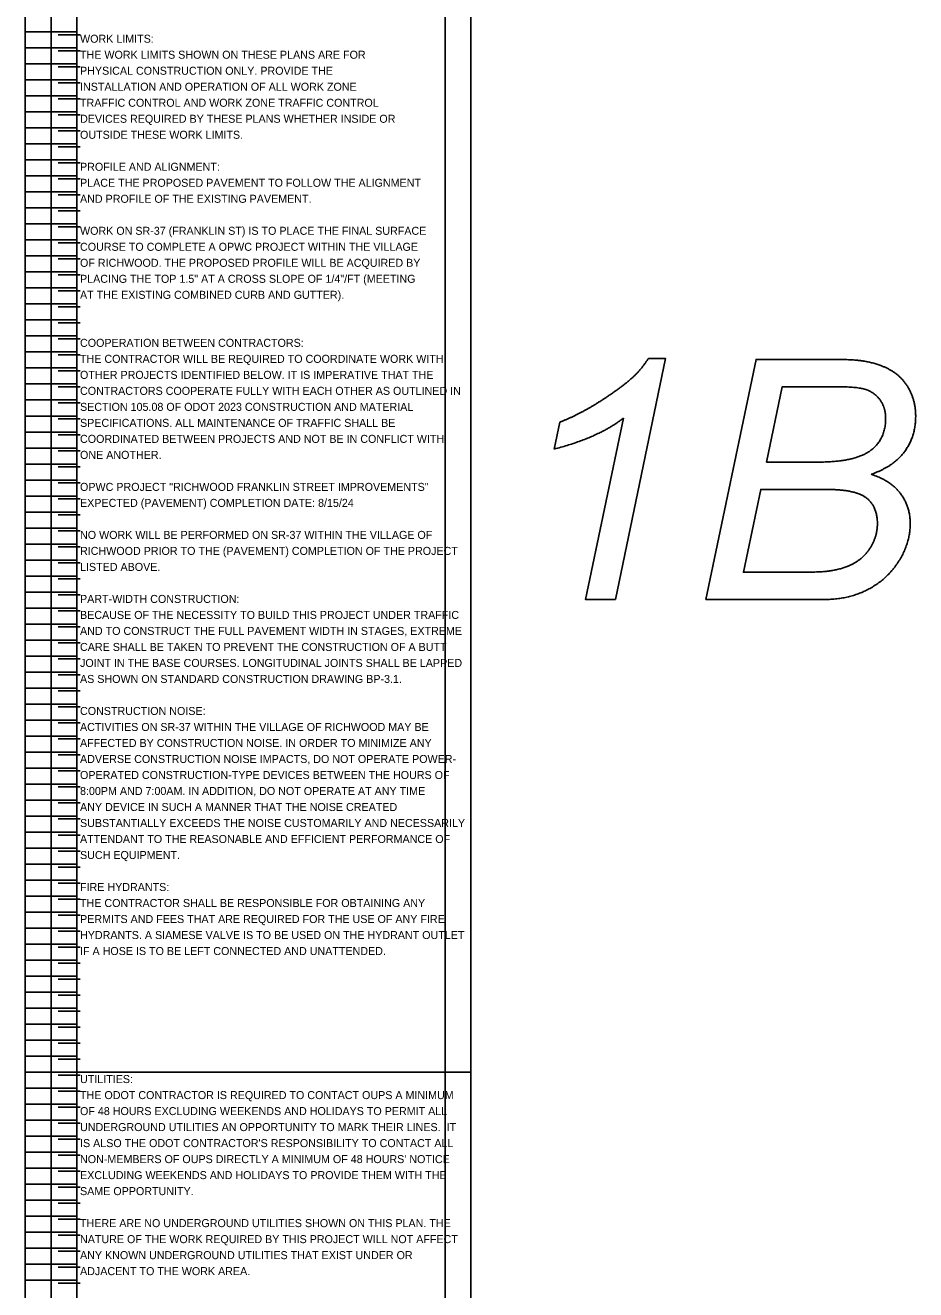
# Model space of a CAD drawing. Extents: x 12316 to 12541, y 1124 to 1850.
# Drawn here: x 12521.92 to 12537.48, y 1805.67 to 1827.79 of the extents above; entities that cross this region are included whole.
import ezdxf

# ---------------------------------------------------------------- set-up
doc = ezdxf.new("R2010")
doc.units = 0
for name, color, linetype in [('SC_Scratch1', 7, 'Continuous'), ('SH_Data', 7, 'Continuous'), ('SH_Text', 7, 'Continuous')]:
    doc.layers.add(name, color=color, linetype=linetype)

msp = doc.modelspace()

# ---------------------------------------------------------------- linework, layer by layer
at = {"layer": 'SC_Scratch1'}
for p, q in [((12521.919, 1809.471), (12521.919, 1829.631)), ((12522.819, 1809.471), (12522.819, 1829.631)), ((12522.819, 1809.471), (12522.819, 1829.631)), ((12522.819, 1829.631), (12522.819, 1809.471)), ((12529.259, 1829.631), (12529.259, 1809.471)), ((12521.919, 1827.671), (12522.819, 1827.671)), ((12522.876, 1827.621), (12522.492, 1827.621)), ((12521.919, 1827.391), (12522.819, 1827.391)), ((12522.876, 1827.341), (12522.492, 1827.341)), ((12521.919, 1827.111), (12522.819, 1827.111)), ((12522.876, 1827.061), (12522.492, 1827.061)), ((12521.919, 1826.831), (12522.819, 1826.831)), ((12522.876, 1826.781), (12522.492, 1826.781)), ((12521.919, 1826.551), (12522.819, 1826.551)), ((12522.876, 1826.501), (12522.492, 1826.501)), ((12521.919, 1826.271), (12522.819, 1826.271)), ((12522.876, 1826.221), (12522.492, 1826.221)), ((12521.919, 1825.991), (12522.819, 1825.991)), ((12522.876, 1825.941), (12522.492, 1825.941)), ((12521.919, 1825.711), (12522.819, 1825.711)), ((12522.876, 1825.661), (12522.492, 1825.661)), ((12521.919, 1825.431), (12522.819, 1825.431)), ((12522.876, 1825.381), (12522.492, 1825.381)), ((12521.919, 1825.151), (12522.819, 1825.151)), ((12522.876, 1825.101), (12522.492, 1825.101)), ((12521.919, 1824.871), (12522.819, 1824.871)), ((12522.876, 1824.821), (12522.492, 1824.821)), ((12521.919, 1824.591), (12522.819, 1824.591)), ((12522.876, 1824.541), (12522.492, 1824.541)), ((12521.919, 1824.311), (12522.819, 1824.311)), ((12522.876, 1824.261), (12522.492, 1824.261)), ((12521.919, 1824.031), (12522.819, 1824.031)), ((12522.876, 1823.981), (12522.492, 1823.981)), ((12521.919, 1823.751), (12522.819, 1823.751)), ((12522.876, 1823.701), (12522.492, 1823.701)), ((12521.919, 1823.471), (12522.819, 1823.471)), ((12522.876, 1823.421), (12522.492, 1823.421)), ((12521.919, 1823.191), (12522.819, 1823.191)), ((12522.876, 1823.141), (12522.492, 1823.141)), ((12521.919, 1822.911), (12522.819, 1822.911)), ((12522.876, 1822.861), (12522.492, 1822.861)), ((12521.919, 1822.631), (12522.819, 1822.631)), ((12522.876, 1822.581), (12522.492, 1822.581)), ((12521.919, 1822.351), (12522.819, 1822.351)), ((12522.876, 1822.301), (12522.492, 1822.301)), ((12521.919, 1822.071), (12522.819, 1822.071)), ((12522.876, 1822.021), (12522.492, 1822.021)), ((12521.919, 1821.791), (12522.819, 1821.791)), ((12522.876, 1821.741), (12522.492, 1821.741)), ((12521.919, 1821.511), (12522.819, 1821.511)), ((12522.876, 1821.461), (12522.492, 1821.461)), ((12521.919, 1821.231), (12522.819, 1821.231)), ((12522.876, 1821.181), (12522.492, 1821.181)), ((12521.919, 1820.951), (12522.819, 1820.951)), ((12522.876, 1820.901), (12522.492, 1820.901)), ((12531.166, 1820.372), (12531.263, 1820.843)), ((12521.919, 1820.671), (12522.819, 1820.671)), ((12522.876, 1820.621), (12522.492, 1820.621)), ((12521.919, 1820.391), (12522.819, 1820.391)), ((12522.876, 1820.341), (12522.492, 1820.341)), ((12521.919, 1820.111), (12522.819, 1820.111)), ((12522.876, 1820.061), (12522.492, 1820.061)), ((12521.919, 1819.831), (12522.819, 1819.831)), ((12522.876, 1819.781), (12522.492, 1819.781)), ((12521.919, 1819.551), (12522.819, 1819.551)), ((12522.876, 1819.501), (12522.492, 1819.501)), ((12521.919, 1819.271), (12522.819, 1819.271)), ((12522.876, 1819.221), (12522.492, 1819.221)), ((12521.919, 1818.991), (12522.819, 1818.991)), ((12522.876, 1818.941), (12522.492, 1818.941)), ((12521.919, 1818.711), (12522.819, 1818.711)), ((12522.876, 1818.661), (12522.492, 1818.661)), ((12521.919, 1818.431), (12522.819, 1818.431)), ((12522.876, 1818.381), (12522.492, 1818.381)), ((12521.919, 1818.151), (12522.819, 1818.151)), ((12522.876, 1818.101), (12522.492, 1818.101)), ((12521.919, 1817.871), (12522.819, 1817.871)), ((12522.876, 1817.821), (12522.492, 1817.821)), ((12521.919, 1817.591), (12522.819, 1817.591)), ((12522.876, 1817.541), (12522.492, 1817.541)), ((12521.919, 1817.311), (12522.819, 1817.311)), ((12522.876, 1817.261), (12522.492, 1817.261)), ((12521.919, 1817.031), (12522.819, 1817.031)), ((12522.876, 1816.981), (12522.492, 1816.981)), ((12521.919, 1816.751), (12522.819, 1816.751)), ((12522.876, 1816.701), (12522.492, 1816.701)), ((12521.919, 1816.471), (12522.819, 1816.471)), ((12522.876, 1816.421), (12522.492, 1816.421)), ((12521.919, 1816.191), (12522.819, 1816.191)), ((12522.876, 1816.141), (12522.492, 1816.141)), ((12521.919, 1815.911), (12522.819, 1815.911)), ((12522.876, 1815.861), (12522.492, 1815.861)), ((12521.919, 1815.631), (12522.819, 1815.631)), ((12522.876, 1815.581), (12522.492, 1815.581)), ((12521.919, 1815.351), (12522.819, 1815.351)), ((12522.876, 1815.301), (12522.492, 1815.301)), ((12521.919, 1815.071), (12522.819, 1815.071)), ((12522.876, 1815.021), (12522.492, 1815.021)), ((12521.919, 1814.791), (12522.819, 1814.791)), ((12522.876, 1814.741), (12522.492, 1814.741)), ((12521.919, 1814.511), (12522.819, 1814.511)), ((12522.876, 1814.461), (12522.492, 1814.461)), ((12521.919, 1814.231), (12522.819, 1814.231)), ((12522.876, 1814.181), (12522.492, 1814.181)), ((12521.919, 1813.951), (12522.819, 1813.951)), ((12522.876, 1813.901), (12522.492, 1813.901)), ((12521.919, 1813.671), (12522.819, 1813.671)), ((12522.876, 1813.621), (12522.492, 1813.621)), ((12521.919, 1813.391), (12522.819, 1813.391)), ((12522.876, 1813.341), (12522.492, 1813.341)), ((12521.919, 1813.111), (12522.819, 1813.111)), ((12522.876, 1813.061), (12522.492, 1813.061)), ((12521.919, 1812.831), (12522.819, 1812.831)), ((12522.876, 1812.781), (12522.492, 1812.781)), ((12521.919, 1812.551), (12522.819, 1812.551)), ((12522.876, 1812.501), (12522.492, 1812.501)), ((12521.919, 1812.271), (12522.819, 1812.271)), ((12522.876, 1812.221), (12522.492, 1812.221)), ((12521.919, 1811.991), (12522.819, 1811.991)), ((12522.876, 1811.941), (12522.492, 1811.941)), ((12521.919, 1811.711), (12522.819, 1811.711)), ((12522.876, 1811.661), (12522.492, 1811.661)), ((12521.919, 1811.431), (12522.819, 1811.431)), ((12522.876, 1811.381), (12522.492, 1811.381)), ((12521.919, 1811.151), (12522.819, 1811.151)), ((12522.876, 1811.101), (12522.492, 1811.101)), ((12521.919, 1810.871), (12522.819, 1810.871)), ((12522.876, 1810.821), (12522.492, 1810.821)), ((12521.919, 1810.591), (12522.819, 1810.591)), ((12522.876, 1810.541), (12522.492, 1810.541)), ((12521.919, 1810.311), (12522.819, 1810.311)), ((12522.876, 1810.261), (12522.492, 1810.261)), ((12521.919, 1810.031), (12522.819, 1810.031)), ((12522.876, 1809.981), (12522.492, 1809.981)), ((12521.919, 1809.751), (12522.819, 1809.751)), ((12522.876, 1809.701), (12522.492, 1809.701)), ((12521.919, 1809.471), (12522.819, 1809.471)), ((12521.919, 1789.311), (12521.919, 1809.471)), ((12521.919, 1809.471), (12522.819, 1809.471)), ((12522.876, 1809.421), (12522.492, 1809.421)), ((12529.259, 1809.471), (12522.819, 1809.471)), ((12522.819, 1789.311), (12522.819, 1809.471)), ((12522.819, 1809.471), (12529.259, 1809.471)), ((12522.819, 1789.311), (12522.819, 1809.471)), ((12522.819, 1809.471), (12522.819, 1789.311)), ((12529.259, 1809.471), (12529.259, 1789.311)), ((12521.919, 1809.191), (12522.819, 1809.191)), ((12522.876, 1809.141), (12522.492, 1809.141)), ((12521.919, 1808.911), (12522.819, 1808.911)), ((12522.876, 1808.861), (12522.492, 1808.861)), ((12521.919, 1808.631), (12522.819, 1808.631)), ((12522.876, 1808.581), (12522.492, 1808.581)), ((12521.919, 1808.351), (12522.819, 1808.351)), ((12522.876, 1808.301), (12522.492, 1808.301)), ((12521.919, 1808.071), (12522.819, 1808.071)), ((12522.876, 1808.021), (12522.492, 1808.021)), ((12521.919, 1807.791), (12522.819, 1807.791)), ((12522.876, 1807.741), (12522.492, 1807.741)), ((12521.919, 1807.511), (12522.819, 1807.511)), ((12522.876, 1807.461), (12522.492, 1807.461)), ((12521.919, 1807.231), (12522.819, 1807.231)), ((12522.876, 1807.181), (12522.492, 1807.181)), ((12521.919, 1806.951), (12522.819, 1806.951)), ((12522.876, 1806.901), (12522.492, 1806.901)), ((12521.919, 1806.671), (12522.819, 1806.671)), ((12522.876, 1806.621), (12522.492, 1806.621)), ((12521.919, 1806.391), (12522.819, 1806.391)), ((12522.876, 1806.341), (12522.492, 1806.341)), ((12521.919, 1806.111), (12522.819, 1806.111)), ((12522.876, 1806.061), (12522.492, 1806.061)), ((12521.919, 1805.831), (12522.819, 1805.831)), ((12522.876, 1805.781), (12522.492, 1805.781))]:
    msp.add_line(p, q, dxfattribs=at)
for points in [[(12522.369, 1829.631), (12529.709, 1829.631), (12529.709, 1809.471), (12522.369, 1809.471)], [(12522.369, 1809.471), (12529.709, 1809.471), (12529.709, 1789.311), (12522.369, 1789.311)]]:
    msp.add_lwpolyline(points, close=True, dxfattribs=at)
for points in [[(12532.811, 1821.957), (12533.111, 1821.957), (12532.234, 1817.741), (12531.712, 1817.741), (12532.375, 1820.914)], [(12536.034, 1821.941), (12534.693, 1821.941), (12533.816, 1817.741), (12535.897, 1817.741)], [(12535.771, 1820.145), (12534.877, 1820.145), (12535.152, 1821.464), (12536.09, 1821.464)], [(12535.467, 1818.218), (12534.474, 1818.218), (12534.777, 1819.668), (12535.893, 1819.668)]]:
    msp.add_lwpolyline(points, dxfattribs=at)
for points in [[(12532.593, 1821.68), (12532.707, 1821.794), (12532.811, 1821.957)], [(12536.577, 1821.912), (12536.4, 1821.941), (12536.034, 1821.941)], [(12537.066, 1821.741), (12536.867, 1821.863), (12536.577, 1821.912)], [(12532.027, 1821.246), (12532.404, 1821.494), (12532.593, 1821.68)], [(12537.375, 1821.409), (12537.266, 1821.62), (12537.066, 1821.741)], [(12536.09, 1821.464), (12536.493, 1821.464), (12536.639, 1821.405)], [(12536.639, 1821.405), (12536.785, 1821.346), (12536.872, 1821.217)], [(12537.484, 1820.943), (12537.484, 1821.198), (12537.375, 1821.409)], [(12531.263, 1820.843), (12531.65, 1820.997), (12532.027, 1821.246)], [(12536.872, 1821.217), (12536.959, 1821.087), (12536.959, 1820.909)], [(12537.293, 1820.332), (12537.484, 1820.596), (12537.484, 1820.943)], [(12532.375, 1820.914), (12531.945, 1820.576), (12531.166, 1820.372)], [(12536.959, 1820.909), (12536.959, 1820.536), (12536.686, 1820.34)], [(12536.686, 1820.34), (12536.413, 1820.145), (12535.771, 1820.145)], [(12536.707, 1819.931), (12537.101, 1820.068), (12537.293, 1820.332)], [(12537.219, 1819.594), (12537.049, 1819.819), (12536.707, 1819.931)], [(12535.893, 1819.668), (12536.437, 1819.668), (12536.626, 1819.515)], [(12537.388, 1819.069), (12537.388, 1819.37), (12537.219, 1819.594)], [(12536.626, 1819.515), (12536.815, 1819.362), (12536.815, 1819.067)], [(12536.815, 1819.067), (12536.815, 1818.87), (12536.717, 1818.69)], [(12537.185, 1818.405), (12537.388, 1818.723), (12537.388, 1819.069)], [(12536.717, 1818.69), (12536.619, 1818.51), (12536.447, 1818.399)], [(12536.447, 1818.399), (12536.275, 1818.289), (12535.998, 1818.244)], [(12536.645, 1817.914), (12536.981, 1818.087), (12537.185, 1818.405)], [(12535.998, 1818.244), (12535.862, 1818.218), (12535.467, 1818.218)], [(12535.897, 1817.741), (12536.31, 1817.741), (12536.645, 1817.914)]]:
    msp.add_open_spline(points, degree=2, dxfattribs=at)

# ---------------------------------------------------------------- texts
at = {"layer": 'SH_Data'}
for s, p in [('COOPERATION BETWEEN CONTRACTORS:', (12522.876, 1822.161)), ('THE CONTRACTOR WILL BE REQUIRED TO COORDINATE WORK WITH ', (12522.876, 1821.881)), ('OTHER PROJECTS IDENTIFIED BELOW. IT IS IMPERATIVE THAT THE ', (12522.876, 1821.601)), ('CONTRACTORS COOPERATE FULLY WITH EACH OTHER AS OUTLINED IN ', (12522.876, 1821.321)), ('SECTION 105.08 OF ODOT 2023 CONSTRUCTION AND MATERIAL ', (12522.876, 1821.041)), ('SPECIFICATIONS. ALL MAINTENANCE OF TRAFFIC SHALL BE ', (12522.876, 1820.761)), ('COORDINATED BETWEEN PROJECTS AND NOT BE IN CONFLICT WITH ', (12522.876, 1820.481)), ('ONE ANOTHER.', (12522.876, 1820.201)), ('OPWC PROJECT "RICHWOOD FRANKLIN STREET IMPROVEMENTS"', (12522.876, 1819.641)), ('EXPECTED (PAVEMENT) COMPLETION DATE: 8/15/24', (12522.876, 1819.361)), ('NO WORK WILL BE PERFORMED ON SR-37 WITHIN THE VILLAGE OF ', (12522.876, 1818.801)), ('RICHWOOD PRIOR TO THE (PAVEMENT) COMPLETION OF THE PROJECT ', (12522.876, 1818.521)), ('LISTED ABOVE. ', (12522.876, 1818.241)), ('PART-WIDTH CONSTRUCTION:', (12522.876, 1817.681)), ('BECAUSE OF THE NECESSITY TO BUILD THIS PROJECT UNDER TRAFFIC ', (12522.876, 1817.401)), ('AND TO CONSTRUCT THE FULL PAVEMENT WIDTH IN STAGES, EXTREME ', (12522.876, 1817.121)), ('CARE SHALL BE TAKEN TO PREVENT THE CONSTRUCTION OF A BUTT ', (12522.876, 1816.841)), ('JOINT IN THE BASE COURSES. LONGITUDINAL JOINTS SHALL BE LAPPED ', (12522.876, 1816.561)), ('AS SHOWN ON STANDARD CONSTRUCTION DRAWING BP-3.1.', (12522.876, 1816.281)), ('CONSTRUCTION NOISE:', (12522.876, 1815.721)), ('ACTIVITIES ON SR-37 WITHIN THE VILLAGE OF RICHWOOD MAY BE ', (12522.876, 1815.441)), ('AFFECTED BY CONSTRUCTION NOISE. IN ORDER TO MINIMIZE ANY ', (12522.876, 1815.161)), ('ADVERSE CONSTRUCTION NOISE IMPACTS, DO NOT OPERATE POWER-', (12522.876, 1814.881)), ('OPERATED CONSTRUCTION-TYPE DEVICES BETWEEN THE HOURS OF ', (12522.876, 1814.601)), ('8:00PM AND 7:00AM. IN ADDITION, DO NOT OPERATE AT ANY TIME ', (12522.876, 1814.321)), ('ANY DEVICE IN SUCH A MANNER THAT THE NOISE CREATED ', (12522.876, 1814.041)), ('SUBSTANTIALLY EXCEEDS THE NOISE CUSTOMARILY AND NECESSARILY ', (12522.876, 1813.761)), ('ATTENDANT TO THE REASONABLE AND EFFICIENT PERFORMANCE OF ', (12522.876, 1813.481)), ('SUCH EQUIPMENT.', (12522.876, 1813.201)), ('FIRE HYDRANTS:', (12522.876, 1812.641)), ('THE CONTRACTOR SHALL BE RESPONSIBLE FOR OBTAINING ANY ', (12522.876, 1812.361)), ('PERMITS AND FEES THAT ARE REQUIRED FOR THE USE OF ANY FIRE ', (12522.876, 1812.081)), ('HYDRANTS. A SIAMESE VALVE IS TO BE USED ON THE HYDRANT OUTLET ', (12522.876, 1811.801)), ('IF A HOSE IS TO BE LEFT CONNECTED AND UNATTENDED.  ', (12522.876, 1811.521)), ('UTILITIES:', (12522.876, 1809.281)), ('THE ODOT CONTRACTOR IS REQUIRED TO CONTACT OUPS A MINIMUM ', (12522.876, 1809.001)), ('OF 48 HOURS EXCLUDING WEEKENDS AND HOLIDAYS TO PERMIT ALL ', (12522.876, 1808.721)), ('UNDERGROUND UTILITIES AN OPPORTUNITY TO MARK THEIR LINES.  IT ', (12522.876, 1808.441)), ("IS ALSO THE ODOT CONTRACTOR'S RESPONSIBILITY TO CONTACT ALL ", (12522.876, 1808.161)), ("NON-MEMBERS OF OUPS DIRECTLY A MINIMUM OF 48 HOURS' NOTICE ", (12522.876, 1807.881)), ('EXCLUDING WEEKENDS AND HOLIDAYS TO PROVIDE THEM WITH THE ', (12522.876, 1807.601)), ('SAME OPPORTUNITY.', (12522.876, 1807.321)), ('THERE ARE NO UNDERGROUND UTILITIES SHOWN ON THIS PLAN. THE ', (12522.876, 1806.761)), ('NATURE OF THE WORK REQUIRED BY THIS PROJECT WILL NOT AFFECT ', (12522.876, 1806.481)), ('ANY KNOWN UNDERGROUND UTILITIES THAT EXIST UNDER OR ', (12522.876, 1806.201)), ('ADJACENT TO THE WORK AREA.', (12522.876, 1805.921))]:
    msp.add_text(s, height=0.14, dxfattribs=at).set_placement(p)
at = {"layer": 'SH_Text'}
for s, p in [('WORK LIMITS:', (12522.876, 1827.481)), ('THE WORK LIMITS SHOWN ON THESE PLANS ARE FOR', (12522.876, 1827.201)), ('PHYSICAL CONSTRUCTION ONLY. PROVIDE THE', (12522.876, 1826.921)), ('INSTALLATION AND OPERATION OF ALL WORK ZONE', (12522.876, 1826.641)), ('TRAFFIC CONTROL AND WORK ZONE TRAFFIC CONTROL', (12522.876, 1826.361)), ('DEVICES REQUIRED BY THESE PLANS WHETHER INSIDE OR', (12522.876, 1826.081)), ('OUTSIDE THESE WORK LIMITS.', (12522.876, 1825.801)), ('PROFILE AND ALIGNMENT:', (12522.876, 1825.241)), ('PLACE THE PROPOSED PAVEMENT TO FOLLOW THE ALIGNMENT ', (12522.876, 1824.961)), ('AND PROFILE OF THE EXISTING PAVEMENT. ', (12522.876, 1824.681)), ('WORK ON SR-37 (FRANKLIN ST) IS TO PLACE THE FINAL SURFACE ', (12522.876, 1824.121)), ('COURSE TO COMPLETE A OPWC PROJECT WITHIN THE VILLAGE ', (12522.876, 1823.841)), ('OF RICHWOOD. THE PROPOSED PROFILE WILL BE ACQUIRED BY ', (12522.876, 1823.561)), ('PLACING THE TOP 1.5" AT A CROSS SLOPE OF 1/4"/FT (MEETING ', (12522.876, 1823.281)), ('AT THE EXISTING COMBINED CURB AND GUTTER).', (12522.876, 1823.001))]:
    msp.add_text(s, height=0.14, dxfattribs=at).set_placement(p)

doc.saveas('drawing.dxf')
